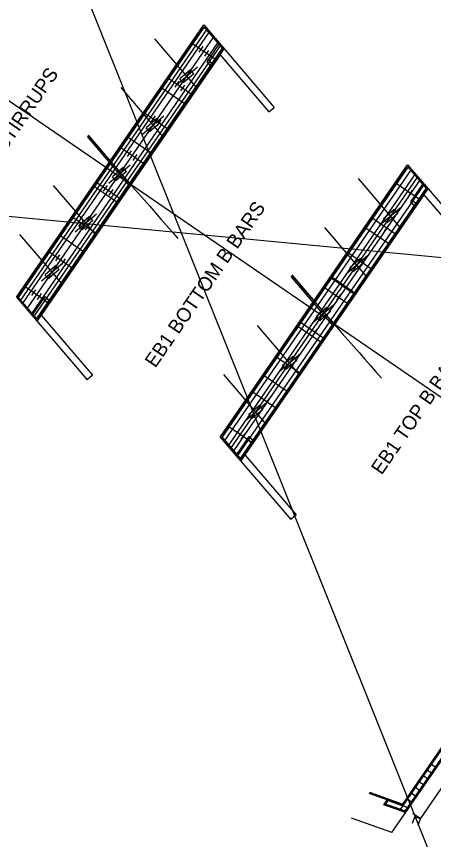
# Model space of a CAD drawing. Extents: x 2378999 to 2381348, y 331302 to 333122.
# Drawn here: x 2379130.1 to 2379189.4, y 331373.2 to 331490.3 of the extents above; entities that cross this region are included whole.
import ezdxf

# ---------------------------------------------------------------- set-up
doc = ezdxf.new("R2010")
doc.units = 0
for name, color, linetype in [('Arrowhead Terminators', 7, 'Continuous'), ('Dimension Lines', 7, 'Continuous'), ('Dimension Lines CELL', 7, 'Continuous'), ('Mis Work Point CELL', 7, 'Continuous'), ('Old_Level_8', 7, 'Continuous'), ('P_SMU_Bent_Cap', 7, 'Continuous'), ('P_SMU_D_Deck_Outline', 7, 'Continuous'), ('P_SMU_Girder_Concrete', 7, 'Continuous'), ('P_SMU_Mis_L_Lines', 7, 'Continuous'), ('P_SMU_Mis_Long_Chord', 7, 'Continuous'), ('P_SMU_Rebar_B_Bar', 7, 'Continuous'), ('P_SMU_Rebar_H_Bar', 7, 'Continuous'), ('P_SMU_Rebar_K_Bar', 7, 'Continuous'), ('P_SMU_Rebar_V_Bar', 7, 'Continuous'), ('Plan Sheet CELL', 7, 'Continuous'), ('Rebar Lines', 7, 'Continuous'), ('Scratch_Level_0', 7, 'Continuous'), ('Sup Concrete Slab Lines', 7, 'Continuous'), ('Text', 7, 'Continuous')]:
    doc.layers.add(name, color=color, linetype=linetype)

msp = doc.modelspace()

# ---------------------------------------------------------------- linework, layer by layer
at = {"layer": 'Arrowhead Terminators'}
for p, q in [((2379130.4, 331450.26), (2379156.82, 331488.72)), ((2379130.72, 331449.89), (2379157.14, 331488.34)), ((2379131.06, 331449.5), (2379157.48, 331487.95)), ((2379158.71, 331486.51), (2379132.29, 331448.05)), ((2379159.05, 331486.11), (2379132.63, 331447.66)), ((2379159.37, 331485.74), (2379132.95, 331447.29)), ((2379159.37, 331430.36), (2379185.79, 331468.81)), ((2379159.75, 331429.92), (2379186.17, 331468.37)), ((2379160.31, 331429.26), (2379186.73, 331467.72)), ((2379187.4, 331466.93), (2379160.98, 331428.48)), ((2379187.96, 331466.27), (2379161.54, 331427.82)), ((2379188.34, 331465.84), (2379161.92, 331427.38))]:
    msp.add_line(p, q, dxfattribs=at)
at = {"layer": 'Dimension Lines'}
for p, q in [((2379216.61, 331301.94), (2379094.44, 331607.27)), ((2379303.66, 331445.13), (2378998.79, 331474.22))]:
    msp.add_line(p, q, dxfattribs=at)
at = {"layer": 'Dimension Lines CELL'}
msp.add_line((2379252.36, 331393.51), (2379066.4, 331521.27), dxfattribs=at)
at = {"layer": 'Mis Work Point CELL'}
for p, q in [((2379131.58, 331448.63), (2379158.19, 331487.37)), ((2379160.55, 331428.73), (2379187.16, 331467.47))]:
    msp.add_line(p, q, dxfattribs=at)
at = {"layer": 'Old_Level_8'}
for p, q in [((2379187.55, 331376.12), (2379186.44, 331376.88)), ((2379186.43, 331375.47), (2379186.76, 331376.4)), ((2379187.22, 331375.19), (2379187.55, 331376.12))]:
    msp.add_line(p, q, dxfattribs=at)
at = {"layer": 'P_SMU_Bent_Cap'}
for p, q in [((2379155.86, 331483.06), (2379152.82, 331480.46)), ((2379151.07, 331476.09), (2379148.03, 331473.49)), ((2379146.28, 331469.12), (2379143.24, 331466.52)), ((2379141.49, 331462.15), (2379138.45, 331459.56)), ((2379184.83, 331463.16), (2379181.79, 331460.56)), ((2379136.71, 331455.19), (2379133.67, 331452.59)), ((2379180.04, 331456.19), (2379177, 331453.59)), ((2379175.25, 331449.22), (2379172.21, 331446.62)), ((2379170.47, 331442.25), (2379167.42, 331439.65)), ((2379165.68, 331435.28), (2379162.64, 331432.68))]:
    msp.add_line(p, q, dxfattribs=at)
at = {"layer": 'P_SMU_D_Deck_Outline'}
for p, q in [((2379154.85, 331482.7), (2379153.33, 331481.4)), ((2379155.34, 331482.12), (2379153.82, 331480.83)), ((2379155.34, 331482.12), (2379154.85, 331482.7)), ((2379153.82, 331480.83), (2379153.33, 331481.4)), ((2379150.07, 331475.73), (2379148.55, 331474.43)), ((2379150.55, 331475.16), (2379149.03, 331473.86)), ((2379150.55, 331475.16), (2379150.07, 331475.73)), ((2379149.03, 331473.86), (2379148.55, 331474.43)), ((2379145.28, 331468.76), (2379143.76, 331467.46)), ((2379145.77, 331468.19), (2379144.25, 331466.89)), ((2379145.77, 331468.19), (2379145.28, 331468.76)), ((2379144.25, 331466.89), (2379143.76, 331467.46)), ((2379183.82, 331462.79), (2379182.3, 331461.49)), ((2379184.31, 331462.22), (2379182.79, 331460.92)), ((2379184.31, 331462.22), (2379183.82, 331462.79)), ((2379140.49, 331461.79), (2379138.97, 331460.49)), ((2379140.98, 331461.22), (2379139.46, 331459.92)), ((2379140.98, 331461.22), (2379140.49, 331461.79)), ((2379182.79, 331460.92), (2379182.3, 331461.49)), ((2379139.46, 331459.92), (2379138.97, 331460.49)), ((2379179.04, 331455.82), (2379177.52, 331454.52)), ((2379179.52, 331455.25), (2379178, 331453.95)), ((2379179.52, 331455.25), (2379179.04, 331455.82)), ((2379135.7, 331454.82), (2379134.18, 331453.52)), ((2379136.19, 331454.25), (2379134.67, 331452.95)), ((2379136.19, 331454.25), (2379135.7, 331454.82)), ((2379178, 331453.95), (2379177.52, 331454.52)), ((2379134.67, 331452.95), (2379134.18, 331453.52)), ((2379174.25, 331448.85), (2379172.73, 331447.55)), ((2379174.74, 331448.28), (2379173.22, 331446.98)), ((2379174.74, 331448.28), (2379174.25, 331448.85)), ((2379173.22, 331446.98), (2379172.73, 331447.55)), ((2379169.46, 331441.89), (2379167.94, 331440.59)), ((2379169.95, 331441.32), (2379168.43, 331440.02)), ((2379169.95, 331441.32), (2379169.46, 331441.89)), ((2379168.43, 331440.02), (2379167.94, 331440.59)), ((2379164.67, 331434.92), (2379163.15, 331433.62)), ((2379165.16, 331434.35), (2379163.64, 331433.05)), ((2379165.16, 331434.35), (2379164.67, 331434.92)), ((2379163.64, 331433.05), (2379163.15, 331433.62))]:
    msp.add_line(p, q, dxfattribs=at)
at = {"layer": 'P_SMU_Girder_Concrete'}
for p, q in [((2379156.09, 331485.18), (2379156.65, 331486)), ((2379156.37, 331485.59), (2379157.18, 331485.03)), ((2379156.9, 331484.62), (2379157.46, 331485.44)), ((2379152.69, 331480.23), (2379153.26, 331481.06)), ((2379152.97, 331480.64), (2379153.78, 331480.09)), ((2379153.5, 331479.67), (2379154.07, 331480.5)), ((2379149.29, 331475.29), (2379149.86, 331476.11)), ((2379149.58, 331475.7), (2379150.39, 331475.14)), ((2379150.1, 331474.73), (2379150.67, 331475.55)), ((2379145.89, 331470.34), (2379146.46, 331471.16)), ((2379146.18, 331470.75), (2379146.99, 331470.2)), ((2379146.7, 331469.78), (2379147.27, 331470.61)), ((2379142.5, 331465.39), (2379143.06, 331466.22)), ((2379142.78, 331465.81), (2379143.59, 331465.25)), ((2379143.31, 331464.84), (2379143.87, 331465.66)), ((2379185.06, 331465.27), (2379185.62, 331466.1)), ((2379185.34, 331465.68), (2379186.15, 331465.13)), ((2379185.87, 331464.72), (2379186.43, 331465.54)), ((2379139.1, 331460.45), (2379139.67, 331461.27)), ((2379181.66, 331460.33), (2379182.23, 331461.15)), ((2379139.38, 331460.86), (2379140.19, 331460.3)), ((2379139.91, 331459.89), (2379140.48, 331460.72)), ((2379181.94, 331460.74), (2379182.75, 331460.18)), ((2379182.47, 331459.77), (2379183.04, 331460.59)), ((2379135.7, 331455.5), (2379136.27, 331456.33)), ((2379135.98, 331455.92), (2379136.8, 331455.36)), ((2379136.51, 331454.95), (2379137.08, 331455.77)), ((2379178.26, 331455.38), (2379178.83, 331456.21)), ((2379178.55, 331455.79), (2379179.36, 331455.24)), ((2379179.07, 331454.82), (2379179.64, 331455.65)), ((2379132.3, 331450.56), (2379132.87, 331451.38)), ((2379132.59, 331450.97), (2379133.4, 331450.41)), ((2379133.11, 331450), (2379133.68, 331450.83)), ((2379174.86, 331450.44), (2379175.43, 331451.26)), ((2379175.15, 331450.85), (2379175.96, 331450.29)), ((2379175.68, 331449.88), (2379176.24, 331450.7)), ((2379171.47, 331445.49), (2379172.03, 331446.32)), ((2379171.75, 331445.9), (2379172.56, 331445.35)), ((2379172.28, 331444.93), (2379172.84, 331445.76)), ((2379168.07, 331440.55), (2379168.64, 331441.37)), ((2379168.35, 331440.96), (2379169.16, 331440.4)), ((2379168.88, 331439.99), (2379169.45, 331440.81)), ((2379164.67, 331435.6), (2379165.24, 331436.42)), ((2379164.96, 331436.01), (2379165.77, 331435.46)), ((2379165.48, 331435.04), (2379166.05, 331435.87)), ((2379161.27, 331430.65), (2379161.84, 331431.48)), ((2379161.56, 331431.07), (2379162.37, 331430.51)), ((2379162.08, 331430.1), (2379162.65, 331430.92))]:
    msp.add_line(p, q, dxfattribs=at)
at = {"layer": 'P_SMU_Mis_L_Lines'}
for p, q in [((2379155.79, 331480.06), (2379149.76, 331487.11)), ((2379151.01, 331473.09), (2379144.98, 331480.15)), ((2379146.22, 331466.12), (2379140.19, 331473.18)), ((2379184.76, 331460.15), (2379178.73, 331467.21)), ((2379141.43, 331459.15), (2379135.4, 331466.21)), ((2379179.98, 331453.18), (2379173.95, 331460.24)), ((2379136.64, 331452.18), (2379130.61, 331459.24)), ((2379175.19, 331446.21), (2379169.16, 331453.27)), ((2379170.4, 331439.25), (2379164.37, 331446.3)), ((2379165.61, 331432.28), (2379159.58, 331439.34))]:
    msp.add_line(p, q, dxfattribs=at)
at = {"layer": 'P_SMU_Mis_Long_Chord'}
for centre in [(2384478.63, 336123.95), (2384507.6, 336104.04)]:
    msp.add_arc(centre, 7080, 221.06156, 221.218654, dxfattribs=at)
at = {"layer": 'P_SMU_Rebar_B_Bar'}
for p, q in [((2379130.12, 331450.34), (2379156.73, 331489.08)), ((2379156.73, 331489.08), (2379166.77, 331477.33)), ((2379158.98, 331486.45), (2379157.16, 331483.81)), ((2379159.06, 331484.81), (2379159.65, 331485.66)), ((2379159.06, 331484.81), (2379133.62, 331447.78)), ((2379159.06, 331484.81), (2379166.01, 331476.68)), ((2379150.65, 331480.22), (2379154.22, 331477.76)), ((2379166.01, 331476.68), (2379166.77, 331477.33)), ((2379145.83, 331473.21), (2379149.41, 331470.76)), ((2379159.09, 331430.43), (2379185.7, 331469.17)), ((2379185.7, 331469.17), (2379195.74, 331457.42)), ((2379141.02, 331466.2), (2379144.59, 331463.75)), ((2379187.95, 331466.55), (2379186.13, 331463.9)), ((2379188.03, 331464.91), (2379188.62, 331465.76)), ((2379188.03, 331464.91), (2379162.59, 331427.88)), ((2379188.03, 331464.91), (2379194.98, 331456.77)), ((2379179.62, 331460.31), (2379183.19, 331457.86)), ((2379136.21, 331459.2), (2379139.78, 331456.74)), ((2379174.8, 331453.31), (2379178.38, 331450.85)), ((2379132.36, 331447.71), (2379134.21, 331450.41)), ((2379130.12, 331450.34), (2379140.16, 331438.59)), ((2379133.62, 331447.78), (2379133.03, 331446.93)), ((2379133.62, 331447.78), (2379140.92, 331439.24)), ((2379169.99, 331446.3), (2379173.56, 331443.85)), ((2379140.92, 331439.24), (2379140.16, 331438.59)), ((2379165.18, 331439.29), (2379168.75, 331436.84)), ((2379161.33, 331427.81), (2379163.19, 331430.51)), ((2379159.09, 331430.43), (2379169.13, 331418.69)), ((2379162.59, 331427.88), (2379162, 331427.02)), ((2379162.59, 331427.88), (2379169.89, 331419.34)), ((2379169.89, 331419.34), (2379169.13, 331418.69)), ((2379185.04, 331378.19), (2379191.4, 331387.45)), ((2379183.47, 331374.14), (2379192.22, 331386.88)), ((2379180.29, 331379.87), (2379185.04, 331378.19)), ((2379185.43, 331376.99), (2379182.34, 331378.08)), ((2379183.47, 331374.14), (2379177.75, 331376.17))]:
    msp.add_line(p, q, dxfattribs=at)
for points in [[(2379157.38, 331484.13), (2379157.16, 331483.81), (2379157.84, 331483.03), (2379158.06, 331483.35)], [(2379186.35, 331464.22), (2379186.13, 331463.9), (2379186.81, 331463.13), (2379187.03, 331463.45)], [(2379134.21, 331450.41), (2379134.89, 331449.63), (2379134.68, 331449.32), (2379134, 331450.09)], [(2379163.19, 331430.51), (2379163.86, 331429.73), (2379163.65, 331429.41), (2379162.97, 331430.19)]]:
    msp.add_lwpolyline(points, close=True, dxfattribs=at)
for centre, radius, start, end in [((2384478.63, 336123.95), 7060.38, 221.087305, 221.095684), ((2384478.63, 336123.95), 7060, 221.086523, 221.094902), ((2384507.6, 336104.04), 7060.38, 221.087305, 221.095684), ((2384507.6, 336104.04), 7060, 221.086523, 221.094902), ((2384478.63, 336123.95), 7099.63, 221.16875, 221.177079), ((2384478.63, 336123.95), 7100, 221.169523, 221.177852), ((2384507.6, 336104.04), 7099.63, 221.16875, 221.177079), ((2384507.6, 336104.04), 7100, 221.169523, 221.177852), ((2373284.82, 335330.79), 7099.63, 326.16875, 326.177079)]:
    msp.add_arc(centre, radius, start, end, dxfattribs=at)
at = {"layer": 'P_SMU_Rebar_H_Bar'}
for p, q in [((2379184.71, 331377.42), (2379191.44, 331387.21)), ((2379185.36, 331377.19), (2379191.99, 331386.84)), ((2379187.55, 331376.12), (2379194.28, 331385.91)), ((2379184.71, 331377.42), (2379183.93, 331377.7)), ((2379185.36, 331377.19), (2379184.58, 331377.47)), ((2379187.55, 331376.12), (2379186.76, 331376.4))]:
    msp.add_line(p, q, dxfattribs=at)
at = {"layer": 'P_SMU_Rebar_K_Bar'}
for p, q in [((2379182.62, 331378.2), (2379185.39, 331377.22)), ((2379182.96, 331378.7), (2379185.73, 331377.72))]:
    msp.add_line(p, q, dxfattribs=at)
at = {"layer": 'P_SMU_Rebar_V_Bar'}
for centre in [(2379189.15, 331383.84), (2379188.58, 331383.01), (2379189.09, 331382.66), (2379187.45, 331381.36), (2379188.01, 331382.19), (2379188.53, 331381.83), (2379186.88, 331380.54), (2379187.4, 331380.19), (2379187.96, 331381.01), (2379186.31, 331379.72), (2379186.83, 331379.36), (2379182.63, 331378.18), (2379182.99, 331378.71), (2379183.42, 331377.9), (2379183.77, 331378.44), (2379184.56, 331378.16), (2379185.11, 331377.96), (2379185.72, 331377.75), (2379185.75, 331378.89), (2379186.26, 331378.54), (2379184.2, 331377.62), (2379184.74, 331377.43), (2379185.35, 331377.21)]:
    msp.add_circle(centre, 0.0208, dxfattribs=at)
at = {"layer": 'Plan Sheet CELL'}
for p, q in [((2379146.37, 331466.33), (2379140.33, 331473.39)), ((2379175.34, 331446.43), (2379169.3, 331453.49))]:
    msp.add_line(p, q, dxfattribs=at)
at = {"layer": 'Rebar Lines'}
for p, q in [((2379154.99, 331486.54), (2379158.56, 331484.08)), ((2379151.59, 331481.59), (2379155.16, 331479.14)), ((2379148.19, 331476.65), (2379151.77, 331474.19)), ((2379144.8, 331471.7), (2379148.37, 331469.25)), ((2379141.4, 331466.76), (2379144.97, 331464.3)), ((2379183.96, 331466.63), (2379187.53, 331464.18)), ((2379138, 331461.81), (2379141.57, 331459.36)), ((2379180.56, 331461.69), (2379184.13, 331459.23)), ((2379134.6, 331456.86), (2379138.18, 331454.41)), ((2379177.17, 331456.74), (2379180.74, 331454.29)), ((2379131.21, 331451.92), (2379134.78, 331449.47)), ((2379173.77, 331451.8), (2379177.34, 331449.34)), ((2379170.37, 331446.85), (2379173.94, 331444.4)), ((2379166.97, 331441.91), (2379170.54, 331439.45)), ((2379163.57, 331436.96), (2379167.15, 331434.51)), ((2379160.18, 331432.02), (2379163.75, 331429.56))]:
    msp.add_line(p, q, dxfattribs=at)
at = {"layer": 'Scratch_Level_0'}
for p, q in [((2379130.33, 331450.35), (2379156.75, 331488.8)), ((2379156.75, 331488.8), (2379159.44, 331485.65)), ((2379159.44, 331485.65), (2379133.02, 331447.2)), ((2379159.3, 331430.44), (2379185.72, 331468.9)), ((2379185.72, 331468.9), (2379188.41, 331465.75)), ((2379188.41, 331465.75), (2379161.99, 331427.3)), ((2379174.71, 331453.17), (2379178.28, 331450.71)), ((2379130.33, 331450.35), (2379133.02, 331447.2)), ((2379159.3, 331430.44), (2379161.99, 331427.3)), ((2379188.99, 331383.94), (2379189.81, 331383.38)), ((2379188.42, 331383.12), (2379189.25, 331382.55)), ((2379187.29, 331381.47), (2379188.12, 331380.9)), ((2379187.86, 331382.29), (2379188.68, 331381.73)), ((2379186.73, 331380.65), (2379187.55, 331380.08)), ((2379180.19, 331379.73), (2379184.98, 331378.03)), ((2379185.59, 331379), (2379186.42, 331378.43)), ((2379186.16, 331379.82), (2379186.98, 331379.26)), ((2379185.48, 331377.15), (2379182.4, 331378.24))]:
    msp.add_line(p, q, dxfattribs=at)
msp.add_arc((2373284.82, 335330.79), 7099.79, 326.16875, 326.177079, dxfattribs=at)
at = {"layer": 'Text'}
for p, q in [((2379144.89, 331468.02), (2379144.89, 331468.02)), ((2379173.86, 331448.11), (2379173.86, 331448.11))]:
    msp.add_line(p, q, dxfattribs=at)

# ---------------------------------------------------------------- texts
at = {"layer": 'Sup Concrete Slab Lines'}
for s, p in [('EB1 STIRRUPS', (2379125.23, 331466.18)), ('EB1 BOTTOM B BARS', (2379149.86, 331440.16)), ('EB1 TOP B BARS', (2379182.03, 331424.93))]:
    msp.add_text(s, height=2, rotation=55.5093, dxfattribs=at).set_placement(p)

doc.saveas('drawing.dxf')
